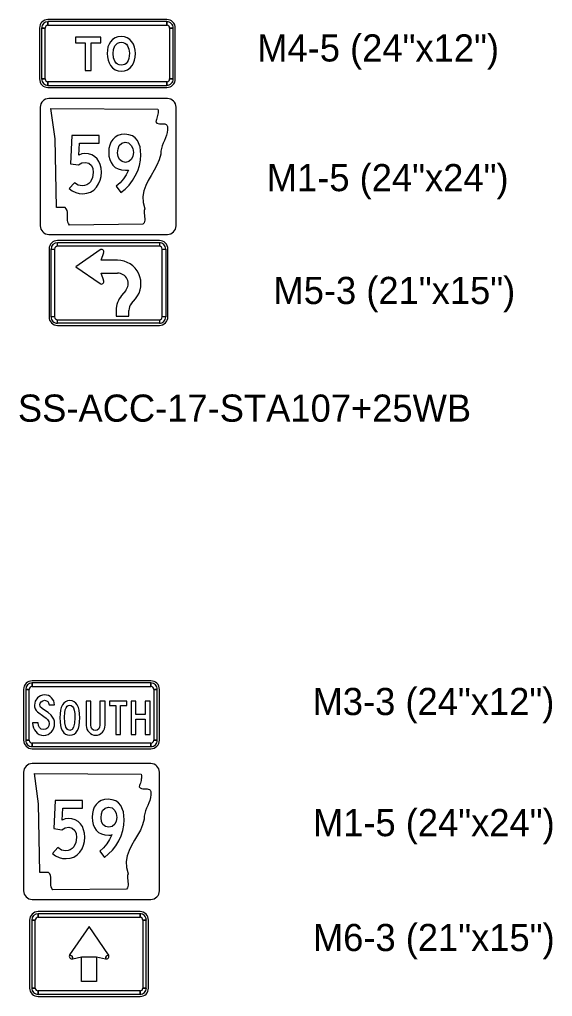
# Model space of a CAD drawing. Extents: x 620856.8 to 620948.6, y 415598.8 to 415658.2.
# Drawn here: x 620919.76 to 620927.61, y 415641.31 to 415655.69 of the extents above; entities that cross this region are included whole.
import ezdxf

# ---------------------------------------------------------------- set-up
doc = ezdxf.new("R2010")
doc.units = 0
doc.layers.add('SIGNS', color=7, linetype='Continuous')

msp = doc.modelspace()

# ---------------------------------------------------------------- linework, layer by layer
at = {"layer": 'SIGNS'}
for p, q in [((620921.933, 415655.694), (620920.183, 415655.694)), ((620920.183, 415655.611), (620920.183, 415655.663)), ((620921.933, 415655.663), (620921.933, 415655.611)), ((620920.058, 415655.569), (620920.058, 415654.819)), ((620920.089, 415655.569), (620920.141, 415655.569)), ((620921.974, 415655.569), (620922.027, 415655.569)), ((620922.058, 415654.819), (620922.058, 415655.569)), ((620920.141, 415654.819), (620920.089, 415654.819)), ((620920.183, 415654.725), (620920.183, 415654.778)), ((620921.933, 415654.778), (620921.933, 415654.725)), ((620922.027, 415654.819), (620921.974, 415654.819)), ((620920.183, 415654.694), (620921.933, 415654.694)), ((620921.944, 415654.53), (620920.194, 415654.53)), ((620920.069, 415654.405), (620920.069, 415652.655)), ((620922.069, 415652.655), (620922.069, 415654.405)), ((620920.069, 415652.655), (620920.069, 415652.655)), ((620920.194, 415652.53), (620921.944, 415652.53)), ((620921.823, 415652.439), (620920.323, 415652.439)), ((620920.198, 415652.314), (620920.198, 415651.314)), ((620920.229, 415652.314), (620920.281, 415652.314)), ((620920.323, 415652.356), (620920.323, 415652.408)), ((620920.949, 415652.303), (620920.593, 415652.054)), ((620921.823, 415652.408), (620921.823, 415652.356)), ((620921.864, 415652.314), (620921.916, 415652.314)), ((620921.948, 415651.314), (620921.948, 415652.314)), ((620920.965, 415652.148), (620921.003, 415652.261)), ((620921.208, 415652.148), (620920.965, 415652.148)), ((620920.593, 415652.054), (620920.949, 415651.804)), ((620921.003, 415651.847), (620920.965, 415651.96)), ((620920.965, 415651.96), (620921.208, 415651.96)), ((620921.328, 415651.703), (620921.267, 415651.632)), ((620921.411, 415651.511), (620921.471, 415651.583)), ((620920.281, 415651.314), (620920.229, 415651.314)), ((620921.187, 415651.41), (620921.187, 415651.325)), ((620921.187, 415651.325), (620921.374, 415651.325)), ((620921.374, 415651.325), (620921.374, 415651.41)), ((620921.916, 415651.314), (620921.864, 415651.314)), ((620920.323, 415651.22), (620920.323, 415651.273)), ((620920.323, 415651.189), (620921.823, 415651.189)), ((620921.823, 415651.273), (620921.823, 415651.22)), ((620921.699, 415645.954), (620919.949, 415645.954)), ((620919.824, 415645.829), (620919.824, 415645.079)), ((620919.855, 415645.829), (620919.907, 415645.829)), ((620919.949, 415645.871), (620919.949, 415645.923)), ((620921.699, 415645.923), (620921.699, 415645.871)), ((620921.74, 415645.829), (620921.792, 415645.829)), ((620921.824, 415645.079), (620921.824, 415645.829)), ((620919.907, 415645.079), (620919.855, 415645.079)), ((620919.949, 415644.986), (620919.949, 415645.038)), ((620919.949, 415644.954), (620921.699, 415644.954)), ((620921.699, 415645.038), (620921.699, 415644.986)), ((620921.792, 415645.079), (620921.74, 415645.079)), ((620921.699, 415644.735), (620919.949, 415644.735)), ((620919.824, 415644.61), (620919.824, 415642.86)), ((620921.824, 415642.86), (620921.824, 415644.61)), ((620919.824, 415642.86), (620919.824, 415642.86)), ((620919.949, 415642.735), (620921.699, 415642.735)), ((620921.538, 415642.555), (620920.038, 415642.555)), ((620920.038, 415642.472), (620920.038, 415642.524)), ((620921.538, 415642.524), (620921.538, 415642.472)), ((620919.913, 415642.43), (620919.913, 415641.43)), ((620919.944, 415642.43), (620919.996, 415642.43)), ((620921.579, 415642.43), (620921.631, 415642.43)), ((620921.663, 415641.43), (620921.663, 415642.43)), ((620920.538, 415641.899), (620920.502, 415641.921)), ((620920.547, 415641.859), (620920.538, 415641.899)), ((620921.038, 415641.899), (620921.028, 415641.859)), ((620921.073, 415641.921), (620921.038, 415641.899)), ((620919.996, 415641.43), (620919.944, 415641.43)), ((620920.038, 415641.337), (620920.038, 415641.389)), ((620921.538, 415641.389), (620921.538, 415641.337)), ((620921.631, 415641.43), (620921.579, 415641.43)), ((620920.038, 415641.305), (620921.538, 415641.305))]:
    msp.add_line(p, q, dxfattribs=at)
for points in [[(620921.933, 415655.663), (620920.183, 415655.663), (620920.183, 415655.611), (620921.933, 415655.611), (620921.933, 415655.663), (620921.933, 415655.663)], [(620920.089, 415655.569), (620920.089, 415654.819), (620920.141, 415654.819), (620920.141, 415655.569), (620920.089, 415655.569), (620920.089, 415655.569)], [(620922.027, 415654.819), (620922.027, 415655.569), (620921.974, 415655.569), (620921.974, 415654.819), (620922.027, 415654.819), (620922.027, 415654.819)], [(620920.73, 415654.944), (620920.817, 415654.944), (620920.817, 415655.352), (620920.96, 415655.352), (620920.96, 415655.435), (620920.589, 415655.435), (620920.589, 415655.352), (620920.73, 415655.352)], [(620920.183, 415654.725), (620921.933, 415654.725), (620921.933, 415654.778), (620920.183, 415654.778), (620920.183, 415654.725), (620920.183, 415654.725)], [(620921.799, 415654.375), (620921.803, 415654.356), (620921.805, 415654.337), (620921.804, 415654.318), (620921.802, 415654.298), (620921.798, 415654.279), (620921.793, 415654.261), (620921.787, 415654.242), (620921.782, 415654.223), (620921.776, 415654.205), (620921.771, 415654.187), (620921.785, 415654.17), (620921.803, 415654.161), (620921.823, 415654.157), (620921.844, 415654.157), (620921.865, 415654.158), (620921.886, 415654.158), (620921.905, 415654.156), (620921.922, 415654.149), (620921.935, 415654.137), (620921.943, 415654.117), (620921.944, 415654.072), (620921.938, 415654.029), (620921.927, 415653.989), (620921.913, 415653.95), (620921.897, 415653.912), (620921.881, 415653.874), (620921.866, 415653.836), (620921.854, 415653.796), (620921.846, 415653.754), (620921.844, 415653.71), (620921.822, 415653.628), (620921.788, 415653.55), (620921.747, 415653.474), (620921.703, 415653.399), (620921.66, 415653.325), (620921.622, 415653.249), (620921.594, 415653.17), (620921.58, 415653.088), (620921.583, 415653), (620921.609, 415652.907), (620921.601, 415652.884), (620921.598, 415652.86), (620921.599, 415652.836), (620921.602, 415652.812), (620921.605, 415652.788), (620921.608, 415652.764), (620921.609, 415652.741), (620921.605, 415652.72), (620921.597, 415652.698), (620921.582, 415652.678), (620920.498, 415652.668), (620920.483, 415652.688), (620920.475, 415652.712), (620920.471, 415652.739), (620920.471, 415652.767), (620920.472, 415652.797), (620920.472, 415652.826), (620920.47, 415652.855), (620920.464, 415652.882), (620920.453, 415652.906), (620920.435, 415652.927), (620920.308, 415652.927), (620920.29, 415653.938), (620920.227, 415654.385), (620921.799, 415654.375), (620921.799, 415654.375)], [(620920.493, 415653.204), (620920.541, 415653.171), (620920.591, 415653.147), (620920.643, 415653.133), (620920.698, 415653.129), (620920.757, 415653.135), (620920.81, 415653.153), (620920.857, 415653.183), (620920.898, 415653.227), (620920.929, 415653.274), (620920.951, 415653.327), (620920.964, 415653.384), (620920.969, 415653.447), (620920.965, 415653.505), (620920.953, 415653.557), (620920.934, 415653.603), (620920.907, 415653.643), (620920.87, 415653.678), (620920.828, 415653.703), (620920.779, 415653.718), (620920.724, 415653.723), (620920.683, 415653.716), (620920.639, 415653.696), (620920.649, 415653.872), (620920.936, 415653.872), (620920.936, 415653.987), (620920.535, 415653.987), (620920.515, 415653.571), (620920.631, 415653.556), (620920.68, 415653.582), (620920.733, 415653.591), (620920.785, 415653.579), (620920.823, 415653.544), (620920.842, 415653.498), (620920.849, 415653.441), (620920.839, 415653.367), (620920.809, 415653.305), (620920.785, 415653.278), (620920.756, 415653.26), (620920.723, 415653.248), (620920.685, 415653.244), (620920.628, 415653.256), (620920.574, 415653.291)], [(620920.281, 415652.314), (620920.281, 415651.314), (620920.229, 415651.314), (620920.229, 415652.314), (620920.281, 415652.314), (620920.281, 415652.314)], [(620921.823, 415652.356), (620920.323, 415652.356), (620920.323, 415652.408), (620921.823, 415652.408), (620921.823, 415652.356), (620921.823, 415652.356)], [(620921.864, 415651.314), (620921.864, 415652.314), (620921.916, 415652.314), (620921.916, 415651.314), (620921.864, 415651.314), (620921.864, 415651.314)], [(620920.323, 415651.273), (620921.823, 415651.273), (620921.823, 415651.22), (620920.323, 415651.22), (620920.323, 415651.273), (620920.323, 415651.273)], [(620919.855, 415645.829), (620919.855, 415645.079), (620919.907, 415645.079), (620919.907, 415645.829), (620919.855, 415645.829), (620919.855, 415645.829)], [(620921.699, 415645.923), (620919.949, 415645.923), (620919.949, 415645.871), (620921.699, 415645.871), (620921.699, 415645.923), (620921.699, 415645.923)], [(620921.792, 415645.079), (620921.792, 415645.829), (620921.74, 415645.829), (620921.74, 415645.079), (620921.792, 415645.079), (620921.792, 415645.079)], [(620919.957, 415645.335), (620919.957, 415645.329), (620919.96, 415645.294), (620919.968, 415645.262), (620919.982, 415645.233), (620920.002, 415645.206), (620920.026, 415645.182), (620920.054, 415645.165), (620920.085, 415645.155), (620920.119, 415645.151), (620920.153, 415645.155), (620920.184, 415645.165), (620920.212, 415645.181), (620920.237, 415645.204), (620920.256, 415645.23), (620920.269, 415645.26), (620920.278, 415645.291), (620920.28, 415645.326), (620920.277, 415645.359), (620920.267, 415645.391), (620920.251, 415645.421), (620920.229, 415645.449), (620920.186, 415645.486), (620920.119, 415645.532), (620920.075, 415645.565), (620920.066, 415645.581), (620920.063, 415645.6), (620920.068, 415645.626), (620920.083, 415645.647), (620920.106, 415645.662), (620920.132, 415645.667), (620920.16, 415645.662), (620920.181, 415645.648), (620920.192, 415645.629), (620920.201, 415645.6), (620920.28, 415645.6), (620920.267, 415645.659), (620920.237, 415645.705), (620920.215, 415645.723), (620920.19, 415645.736), (620920.161, 415645.743), (620920.13, 415645.746), (620920.101, 415645.743), (620920.074, 415645.735), (620920.049, 415645.721), (620920.027, 415645.702), (620919.994, 415645.654), (620919.983, 415645.598), (620919.986, 415645.569), (620919.994, 415645.543), (620920.008, 415645.519), (620920.027, 415645.497), (620920.12, 415645.43), (620920.154, 415645.404), (620920.176, 415645.384), (620920.195, 415645.356), (620920.201, 415645.325), (620920.196, 415645.291), (620920.179, 415645.263), (620920.152, 415645.242), (620920.119, 415645.235), (620920.084, 415645.242), (620920.057, 415645.266), (620920.041, 415645.297), (620920.036, 415645.335)], [(620920.746, 415645.653), (620920.746, 415645.298), (620920.749, 415645.269), (620920.757, 415645.243), (620920.769, 415645.218), (620920.787, 415645.196), (620920.808, 415645.177), (620920.832, 415645.164), (620920.858, 415645.156), (620920.886, 415645.153), (620920.914, 415645.156), (620920.94, 415645.164), (620920.963, 415645.178), (620920.984, 415645.198), (620921.001, 415645.22), (620921.013, 415645.245), (620921.02, 415645.271), (620921.023, 415645.299), (620921.023, 415645.653), (620920.948, 415645.653), (620920.948, 415645.302), (620920.943, 415645.272), (620920.931, 415645.247), (620920.908, 415645.23), (620920.879, 415645.224), (620920.851, 415645.23), (620920.83, 415645.248), (620920.817, 415645.273), (620920.813, 415645.302), (620920.813, 415645.653)], [(620921.18, 415645.163), (620921.251, 415645.163), (620921.251, 415645.591), (620921.343, 415645.591), (620921.343, 415645.653), (620921.09, 415645.653), (620921.09, 415645.591), (620921.18, 415645.591)], [(620921.41, 415645.163), (620921.477, 415645.163), (620921.477, 415645.388), (620921.612, 415645.388), (620921.612, 415645.163), (620921.687, 415645.163), (620921.687, 415645.653), (620921.612, 415645.653), (620921.612, 415645.456), (620921.477, 415645.456), (620921.477, 415645.653), (620921.41, 415645.653)], [(620919.949, 415644.986), (620921.699, 415644.986), (620921.699, 415645.038), (620919.949, 415645.038), (620919.949, 415644.986), (620919.949, 415644.986)], [(620921.554, 415644.581), (620921.558, 415644.562), (620921.56, 415644.542), (620921.559, 415644.523), (620921.557, 415644.504), (620921.553, 415644.485), (620921.548, 415644.466), (620921.543, 415644.447), (620921.537, 415644.429), (620921.531, 415644.411), (620921.526, 415644.392), (620921.541, 415644.376), (620921.558, 415644.367), (620921.578, 415644.363), (620921.599, 415644.362), (620921.62, 415644.363), (620921.641, 415644.364), (620921.66, 415644.361), (620921.677, 415644.355), (620921.69, 415644.343), (620921.698, 415644.323), (620921.699, 415644.277), (620921.693, 415644.235), (620921.682, 415644.194), (620921.668, 415644.156), (620921.652, 415644.118), (620921.636, 415644.08), (620921.621, 415644.041), (620921.609, 415644.002), (620921.601, 415643.96), (620921.599, 415643.916), (620921.577, 415643.834), (620921.543, 415643.756), (620921.502, 415643.68), (620921.458, 415643.605), (620921.415, 415643.531), (620921.377, 415643.455), (620921.349, 415643.376), (620921.335, 415643.293), (620921.338, 415643.206), (620921.364, 415643.112), (620921.356, 415643.089), (620921.353, 415643.065), (620921.354, 415643.042), (620921.357, 415643.017), (620921.36, 415642.993), (620921.363, 415642.97), (620921.364, 415642.947), (620921.36, 415642.925), (620921.352, 415642.904), (620921.337, 415642.884), (620920.253, 415642.874), (620920.238, 415642.894), (620920.23, 415642.918), (620920.226, 415642.944), (620920.226, 415642.973), (620920.227, 415643.002), (620920.227, 415643.032), (620920.225, 415643.061), (620920.219, 415643.087), (620920.208, 415643.112), (620920.19, 415643.132), (620920.063, 415643.132), (620920.045, 415644.144), (620919.982, 415644.591), (620921.554, 415644.581), (620921.554, 415644.581)], [(620920.249, 415643.409), (620920.296, 415643.376), (620920.346, 415643.353), (620920.398, 415643.339), (620920.453, 415643.335), (620920.512, 415643.341), (620920.565, 415643.359), (620920.612, 415643.389), (620920.653, 415643.432), (620920.684, 415643.48), (620920.706, 415643.532), (620920.719, 415643.59), (620920.724, 415643.653), (620920.72, 415643.71), (620920.708, 415643.762), (620920.689, 415643.808), (620920.662, 415643.849), (620920.625, 415643.884), (620920.583, 415643.909), (620920.534, 415643.923), (620920.479, 415643.929), (620920.438, 415643.922), (620920.394, 415643.902), (620920.404, 415644.077), (620920.691, 415644.077), (620920.691, 415644.193), (620920.29, 415644.193), (620920.27, 415643.777), (620920.386, 415643.762), (620920.435, 415643.788), (620920.488, 415643.797), (620920.54, 415643.785), (620920.578, 415643.75), (620920.597, 415643.704), (620920.604, 415643.647), (620920.594, 415643.572), (620920.564, 415643.511), (620920.54, 415643.484), (620920.511, 415643.465), (620920.478, 415643.454), (620920.44, 415643.45), (620920.383, 415643.462), (620920.329, 415643.497)], [(620921.538, 415642.524), (620920.038, 415642.524), (620920.038, 415642.472), (620921.538, 415642.472), (620921.538, 415642.524), (620921.538, 415642.524)], [(620919.944, 415642.43), (620919.944, 415641.43), (620919.996, 415641.43), (620919.996, 415642.43), (620919.944, 415642.43), (620919.944, 415642.43)], [(620921.631, 415641.43), (620921.631, 415642.43), (620921.579, 415642.43), (620921.579, 415641.43), (620921.631, 415641.43), (620921.631, 415641.43)], [(620920.788, 415642.337), (620920.502, 415641.921), (620920.538, 415641.899), (620920.547, 415641.859), (620920.678, 415641.889), (620920.897, 415641.889), (620921.028, 415641.859), (620921.038, 415641.899), (620921.073, 415641.921), (620920.788, 415642.337), (620920.788, 415642.337)], [(620920.897, 415641.524), (620920.678, 415641.524), (620920.678, 415641.889), (620920.897, 415641.889), (620920.897, 415641.524), (620920.897, 415641.524)], [(620920.038, 415641.337), (620921.538, 415641.337), (620921.538, 415641.389), (620920.038, 415641.389), (620920.038, 415641.337), (620920.038, 415641.337)]]:
    msp.add_lwpolyline(points, close=True, dxfattribs=at)
for points in [[(620921.47, 415655.193), (620921.467, 415655.243), (620921.457, 415655.289), (620921.441, 415655.33), (620921.419, 415655.366), (620921.387, 415655.4), (620921.351, 415655.425), (620921.308, 415655.439), (620921.26, 415655.444), (620921.212, 415655.439), (620921.17, 415655.425), (620921.133, 415655.4), (620921.103, 415655.367), (620921.082, 415655.331), (620921.066, 415655.29), (620921.057, 415655.245), (620921.054, 415655.196), (620921.057, 415655.144), (620921.067, 415655.098), (620921.082, 415655.055), (620921.103, 415655.017), (620921.135, 415654.981), (620921.172, 415654.955), (620921.215, 415654.94), (620921.264, 415654.935), (620921.312, 415654.94), (620921.354, 415654.955), (620921.391, 415654.981), (620921.422, 415655.016), (620921.443, 415655.054), (620921.458, 415655.096), (620921.467, 415655.142), (620921.47, 415655.193)], [(620921.381, 415655.2), (620921.379, 415655.158), (620921.373, 415655.122), (620921.364, 415655.092), (620921.351, 415655.067), (620921.335, 415655.048), (620921.315, 415655.034), (620921.291, 415655.025), (620921.264, 415655.023), (620921.233, 415655.026), (620921.207, 415655.037), (620921.186, 415655.054), (620921.168, 415655.079), (620921.15, 415655.13), (620921.143, 415655.193), (620921.15, 415655.255), (620921.169, 415655.305), (620921.186, 415655.329), (620921.208, 415655.346), (620921.234, 415655.356), (620921.264, 415655.36), (620921.292, 415655.356), (620921.317, 415655.346), (620921.338, 415655.33), (620921.355, 415655.307), (620921.374, 415655.259), (620921.381, 415655.2)], [(620920.194, 415654.53), (620920.194, 415654.53)], [(620921.944, 415654.53), (620921.944, 415654.53)], [(620920.069, 415654.405), (620920.069, 415654.405)], [(620921.189, 415653.24), (620921.258, 415653.145), (620921.32, 415653.198), (620921.376, 415653.257), (620921.426, 415653.321), (620921.469, 415653.39), (620921.505, 415653.467), (620921.532, 415653.544), (620921.547, 415653.622), (620921.552, 415653.7), (620921.54, 415653.819), (620921.502, 415653.911), (620921.467, 415653.951), (620921.425, 415653.98), (620921.374, 415653.998), (620921.315, 415654.004), (620921.26, 415653.999), (620921.213, 415653.984), (620921.171, 415653.96), (620921.136, 415653.926), (620921.11, 415653.888), (620921.092, 415653.844), (620921.081, 415653.794), (620921.077, 415653.74), (620921.081, 415653.683), (620921.092, 415653.632), (620921.111, 415653.588), (620921.138, 415653.55), (620921.174, 415653.517), (620921.217, 415653.493), (620921.267, 415653.479), (620921.323, 415653.475), (620921.347, 415653.476), (620921.371, 415653.478), (620921.368, 415653.478), (620921.335, 415653.409), (620921.294, 415653.347), (620921.245, 415653.29), (620921.189, 415653.24)], [(620921.44, 415653.737), (620921.433, 415653.68), (620921.413, 415653.636), (620921.375, 415653.602), (620921.323, 415653.591), (620921.273, 415653.602), (620921.236, 415653.634), (620921.216, 415653.678), (620921.209, 415653.732), (620921.215, 415653.791), (620921.232, 415653.837), (620921.268, 415653.875), (620921.319, 415653.888), (620921.371, 415653.876), (620921.41, 415653.841), (620921.433, 415653.794), (620921.44, 415653.737)], [(620920.194, 415652.53), (620920.194, 415652.53)], [(620921.944, 415652.53), (620921.944, 415652.53)], [(620920.651, 415645.409), (620920.648, 415645.468), (620920.641, 415645.52), (620920.63, 415645.563), (620920.614, 415645.599), (620920.594, 415645.627), (620920.569, 415645.647), (620920.54, 415645.659), (620920.506, 415645.663), (620920.471, 415645.659), (620920.441, 415645.647), (620920.416, 415645.627), (620920.395, 415645.599), (620920.379, 415645.563), (620920.368, 415645.52), (620920.361, 415645.468), (620920.359, 415645.409), (620920.361, 415645.348), (620920.368, 415645.297), (620920.379, 415645.253), (620920.395, 415645.217), (620920.415, 415645.189), (620920.44, 415645.169), (620920.469, 415645.157), (620920.503, 415645.153), (620920.537, 415645.157), (620920.567, 415645.169), (620920.593, 415645.189), (620920.614, 415645.217), (620920.63, 415645.253), (620920.641, 415645.297), (620920.648, 415645.348), (620920.651, 415645.409)], [(620920.58, 415645.411), (620920.575, 415645.329), (620920.561, 415645.271), (620920.537, 415645.236), (620920.503, 415645.224), (620920.47, 415645.237), (620920.445, 415645.274), (620920.431, 415645.336), (620920.426, 415645.423), (620920.429, 415645.481), (620920.438, 415645.529), (620920.45, 415645.558), (620920.464, 415645.58), (620920.482, 415645.592), (620920.503, 415645.597), (620920.525, 415645.592), (620920.542, 415645.578), (620920.557, 415645.555), (620920.568, 415645.523), (620920.577, 415645.472), (620920.58, 415645.411)], [(620919.949, 415644.735), (620919.949, 415644.735)], [(620921.699, 415644.735), (620921.699, 415644.735)], [(620919.824, 415644.61), (620919.824, 415644.61)], [(620920.944, 415643.446), (620921.013, 415643.351), (620921.075, 415643.404), (620921.131, 415643.462), (620921.181, 415643.526), (620921.224, 415643.596), (620921.26, 415643.672), (620921.287, 415643.749), (620921.302, 415643.827), (620921.307, 415643.906), (620921.295, 415644.025), (620921.257, 415644.116), (620921.223, 415644.157), (620921.18, 415644.186), (620921.129, 415644.203), (620921.07, 415644.209), (620921.016, 415644.204), (620920.968, 415644.19), (620920.926, 415644.166), (620920.891, 415644.132), (620920.865, 415644.093), (620920.847, 415644.049), (620920.836, 415644), (620920.832, 415643.946), (620920.836, 415643.888), (620920.847, 415643.838), (620920.866, 415643.793), (620920.893, 415643.755), (620920.929, 415643.722), (620920.972, 415643.699), (620921.022, 415643.685), (620921.078, 415643.68), (620921.102, 415643.682), (620921.126, 415643.684), (620921.123, 415643.684), (620921.09, 415643.615), (620921.049, 415643.552), (620921, 415643.496), (620920.944, 415643.446)], [(620921.195, 415643.943), (620921.188, 415643.886), (620921.168, 415643.841), (620921.13, 415643.808), (620921.078, 415643.797), (620921.028, 415643.807), (620920.992, 415643.839), (620920.971, 415643.883), (620920.964, 415643.938), (620920.97, 415643.996), (620920.987, 415644.043), (620921.023, 415644.081), (620921.074, 415644.094), (620921.126, 415644.082), (620921.165, 415644.046), (620921.188, 415643.999), (620921.195, 415643.943)], [(620919.949, 415642.735), (620919.949, 415642.735)], [(620921.699, 415642.735), (620921.699, 415642.735)]]:
    msp.add_lwpolyline(points, dxfattribs=at)
for centre, radius, start, end in [((620920.183, 415655.569), 0.125, 90.0002, 179.9998), ((620920.183, 415655.569), 0.0937, 90.0002, 179.9998), ((620920.183, 415655.569), 0.0417, 90.0002, 179.9998), ((620921.933, 415655.569), 0.125, 0, 90.0002), ((620921.933, 415655.569), 0.0937, 0, 90.0002), ((620921.933, 415655.569), 0.0417, 0, 90.0002), ((620920.183, 415654.819), 0.125, 179.9998, 270.0001), ((620920.183, 415654.819), 0.0937, 179.9998, 270.0001), ((620920.183, 415654.819), 0.0417, 179.9998, 270.0001), ((620921.933, 415654.819), 0.125, 270.0001, 0.0003), ((620921.933, 415654.819), 0.0937, 270.0001, 0.0003), ((620921.933, 415654.819), 0.0417, 270.0001, 0.0003), ((620920.194, 415654.405), 0.125, 90.0002, 179.9998), ((620921.944, 415654.405), 0.125, 360, 90), ((620920.194, 415652.655), 0.125, 180, 270), ((620921.944, 415652.655), 0.125, 270.0001, 0.0003), ((620920.323, 415652.314), 0.125, 90.0002, 179.9998), ((620921.823, 415652.314), 0.125, 0, 90.0002), ((620920.323, 415652.314), 0.0937, 90.0002, 179.9998), ((620920.323, 415652.314), 0.0417, 90.0002, 179.9998), ((620920.968, 415652.273), 0.0365, 341.5654, 122.8665), ((620921.823, 415652.314), 0.0937, 0, 90.0002), ((620921.823, 415652.314), 0.0417, 0, 90.0002), ((620921.208, 415651.804), 0.344, 320.0027, 90.0056), ((620921.208, 415651.804), 0.156, 319.9975, 89.9999), ((620920.968, 415651.835), 0.0365, 237.1341, 18.4346), ((620921.531, 415651.41), 0.344, 139.9518, 179.954), ((620921.53, 415651.411), 0.156, 140.0372, 180.04), ((620920.323, 415651.314), 0.125, 179.9998, 270.0001), ((620920.323, 415651.314), 0.0937, 179.9998, 270.0001), ((620920.323, 415651.314), 0.0417, 179.9998, 270.0001), ((620921.823, 415651.314), 0.0937, 270.0001, 0.0003), ((620921.823, 415651.314), 0.0417, 270.0001, 0.0003), ((620921.823, 415651.314), 0.125, 270.0001, 0.0003), ((620919.949, 415645.829), 0.125, 90.0002, 179.9998), ((620921.699, 415645.829), 0.125, 360, 90.0002), ((620919.949, 415645.829), 0.0937, 90.0002, 179.9998), ((620919.949, 415645.829), 0.0417, 90.0002, 179.9998), ((620921.699, 415645.829), 0.0937, 360, 90.0002), ((620921.699, 415645.829), 0.0417, 360, 90.0002), ((620919.949, 415645.079), 0.125, 179.9998, 270.0001), ((620919.949, 415645.079), 0.0937, 179.9998, 270.0001), ((620919.949, 415645.079), 0.0417, 179.9998, 270.0001), ((620921.699, 415645.079), 0.125, 270.0001, 0.0003), ((620921.699, 415645.079), 0.0937, 270.0001, 0.0003), ((620921.699, 415645.079), 0.0417, 270.0001, 0.0003), ((620919.949, 415644.61), 0.125, 90.0002, 179.9998), ((620921.699, 415644.61), 0.125, 360, 90), ((620919.949, 415642.86), 0.125, 180, 270), ((620921.699, 415642.86), 0.125, 270.0001, 0.0003), ((620920.038, 415642.43), 0.125, 90.0002, 179.9998), ((620920.038, 415642.43), 0.0937, 90.0002, 179.9998), ((620921.538, 415642.43), 0.125, 360, 90.0002), ((620921.538, 415642.43), 0.0937, 360, 90.0002), ((620920.038, 415642.43), 0.0417, 90.0002, 179.9998), ((620921.538, 415642.43), 0.0417, 360, 90.0002), ((620920.538, 415641.899), 0.0417, 147.7246, 282.9506), ((620921.038, 415641.899), 0.0417, 257.0495, 32.2756), ((620920.038, 415641.43), 0.125, 179.9998, 270.0001), ((620920.038, 415641.43), 0.0937, 179.9998, 270.0001), ((620920.038, 415641.43), 0.0417, 179.9998, 270.0001), ((620921.538, 415641.43), 0.0937, 270.0001, 0.0003), ((620921.538, 415641.43), 0.0417, 270.0001, 0.0003), ((620921.538, 415641.43), 0.125, 270.0001, 0.0003)]:
    msp.add_arc(centre, radius, start, end, dxfattribs=at)

# ---------------------------------------------------------------- texts
for s, p in [('M4-5 (24"x12")', (620923.264, 415655.076)), ('M1-5 (24"x24")', (620923.405, 415653.166)), ('M5-3 (21"x15")', (620923.503, 415651.504)), ('SS-ACC-17-STA107+25WB', (620919.74, 415649.771)), ('M3-3 (24"x12")', (620924.079, 415645.45)), ('M1-5 (24"x24")', (620924.084, 415643.666)), ('M6-3 (21"x15")', (620924.084, 415641.974))]:
    msp.add_text(s, height=0.4, rotation=0, dxfattribs=at).set_placement(p)

doc.saveas('drawing.dxf')
